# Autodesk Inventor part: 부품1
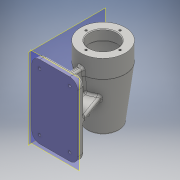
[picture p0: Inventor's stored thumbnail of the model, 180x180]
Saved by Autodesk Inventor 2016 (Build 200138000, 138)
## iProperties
Created: 2018-09
Part Number: 부품1
Material: Generic
Document SubType Name: Modeling
Designer: CAMTIC
Density: 1 g/cm^3
Appearance: Default
Author: CAMTIC
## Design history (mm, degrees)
sketch "스케치1"
  geometry: L1 (0, -79.513)-(0, 78.585) reference; L2 (-6.8, 0)-(40.8, 0) reference; L3 (0, 56)-(34, 56); L4 (34, 56)-(34, 28); L5 (34, 28)-(24.144, -52.27); L6 (0, -56)-(0, 56); A1 r 80 centre (0, 24) between (0, -56) and (24.144, -52.27); 2 further points
  constraints: 8 end point, 4 point on line, 2 point on circle, 1 centre point, 1 collinear, 1 horizontal, 1 vertical
  dimensions: "d0" = 34 distance of L3.start L3.end; "d1" = 28 distance of L3.end L4.end; "d3" = 56 distance between parallel lines of L3 L2; "d4" = 7 deg angle of L4 L5; "d39" = 80 radius of A1; "d40" = 112 distance from line of L3 L6.start
revolve "회전1" sketch "스케치1" stored, may be unused: angle "d5" = 90 deg
node "작업 평면1"
sketch "스케치2"
  geometry: L1 (35, 56)-(-35, 56); L2 (-35, 56)-(-35, -56); L3 (-35, -56)-(35, -56); L4 (35, -56)-(35, 56); L5 (49, 0)-(-49, 0) reference; L6 (0, -78.4)-(0, 78.4) reference; 1 further point
  constraints: 8 end point, 2 parallel, 1 horizontal, 1 perpendicular
  dimensions: "d7" = 112 distance between parallel lines of L3 L1; "d8" = 56 distance between parallel lines of L5 L1; "d9" = 70 distance between parallel lines of L2 L4; "d10" = 35 distance between parallel lines of L6 L4
extrude "돌출1" join sketch "스케치2" distance "d11" = 10; taper "d12" = 0 deg
sketch "스케치3"
  geometry: L1 (-35, -74)-(35, -74); L2 (-34.819, -63.503)-(-18.621, -19); L3 (-18.621, -19)-(18.621, -19); L4 (18.621, -19)-(34.819, -63.503); L5 (35, -74)-(-35, -74); L6 (35, -74)-(-35, -74) reference; L7 (-35, -64)-(35, -64) reference; L8 (35, -74)-(35, -64) reference; L9 (35, -64.529)-(35, -74); L10 (-35, -74)-(35, -74) reference; L11 (35, -74)-(-35, -74); L12 (-35, -74)-(-35, -64) reference; L13 (-35, -74)-(-35, -64.529); L14 (0, -95.6)-(0, 55.6) reference; L15 (-50.061, 0)-(50.061, 0) reference; A1 r 3 centre (32, -64.529) between (35, -64.529) and (34.819, -63.503); A2 r 3 centre (-32, -64.529) between (-34.819, -63.503) and (-35, -64.529); 3 further points
  constraints: 16 end point, 8 point on line, 4 point on circle, 4 tangent, 3 collinear, 2 centre point, 1 equal radius, 1 perpendicular
  dimensions: "d80" = 55 distance between parallel lines of L1 L3; "d81" = 20 deg angle of L4 L8; "d82" = 20 deg angle of L2 L12; "d83" = 36.04216 distance from line of L15.end L4; "d84" = 58.04206 distance from line of L15.end L2; "d85" = 3 radius of A1
extrude "돌출2" join sketch "스케치3" stored distance "d16" = 8; taper "d17" = 0 deg
sketch "스케치4"
  geometry: L1 (-14, 38)-(-64, 38); L2 (-64, -56)-(-64, 56) reference; L3 (-64, 38)-(-64, -38); L4 (-64, -56)-(-64, 56) reference; L5 (-64, -38)-(-14, -24.603); L6 (-14, -24.603)-(-14, 38); L7 (-34, 28)-(34, 28) reference; L8 (-74, 56)-(-64, 56) reference; L9 (-74, -56)-(-64, -56) reference; 3 further points
  constraints: 8 end point, 2 point on line, 1 horizontal, 1 perpendicular
  dimensions: "d18" = 105 deg angle of L4 L5; "d19" = 18 distance between parallel lines of L1 L8; "d20" = 18 distance from line of L3.end L9; "d21" = 50 distance between parallel lines of L3 L6
extrude "돌출3" join sketch "스케치4" stored distance "d22" = 8; taper "d23" = 0 deg
fillet "모깎기1" dims "d24" = 12
sketch "스케치5"
  geometry: L1 (-47.6, 0)-(47.6, 0) reference; L2 (0, -71.2)-(0, 77.2) reference; L3 (16, -47)-(16, -43); L4 (16, -43)-(17.5, -43); L5 (17.5, -43)-(17.5, -25); L6 (17.5, -25)-(21, -25); L7 (21, -25)-(21, -13); L8 (21, -13)-(24, -13); L9 (24, -13)-(24, 41); L10 (24, 41)-(21, 41); L11 (21, 41)-(21, 56); L12 (-34, 56)-(34, 56) reference; L13 (21, 56)-(0, 56); L14 (0, 56)-(0, -50); L15 (16, -47)-(10.5, -47); L16 (10.5, -47)-(10.5, -50); L17 (10.5, -50)-(0, -50); 1 further point
  constraints: 28 end point, 8 perpendicular, 4 point on line, 1 collinear, 1 horizontal, 1 midpoint
  dimensions: "d26" = 21 distance of L11.end L13.end; "d27" = 24 distance between parallel lines of L2 L9; "d29" = 17.5 distance between parallel lines of L2 L5; "d30" = 16 distance between parallel lines of L2 L3; "d31" = 10.5 distance between parallel lines of L2 L16; "d32" = 15 distance between parallel lines of L13 L10; "d33" = 54 distance between parallel lines of L10 L8; "d34" = 12 distance between parallel lines of L8 L6; "d35" = 18 distance between parallel lines of L6 L4; "d36" = 3 distance between parallel lines of L15 L17; "d37" = 4 distance between parallel lines of L4 L15
revolve "회전2" sketch "스케치5" stored, may be unused: angle "d38" = 90 deg
fillet "모깎기3" dims "d41" = 0.3
fillet "모깎기4" dims "d42" = 3
fillet "모깎기5" dims "d43" = 3
chamfer "모따기1" distance "d44" = 1; stored, may be unused: second distance "d45" = 2, angle "d46" = 45 deg
fillet "모깎기6" dims "d47" = 3
fillet "모깎기7" dims "d48" = 3
sketch "스케치6"
  geometry: A1 r 12 centre (-23, 44) between (-23, 56) and (-35, 44) reference; A2 r 12 centre (23, 44) between (35, 44) and (23, 56) reference; A3 r 12 centre (-23, -44) between (-35, -44) and (-23, -56) reference; A4 r 12 centre (23, -44) between (23, -56) and (35, -44) reference; 5 further points
  constraints: 4 coincident
hole "구멍1" sketch "스케치6" at (-23, 44), (23, 44), (-23, -44), (23, -44) diameter "d52" = 4; stored, may be unused: countersink angle "d56" = 90 deg, drill point angle "d58" = 0 deg; dims "d53" = 6, "d54" = 9.5, "d55" = 5.4, "d57" = 8
sketch "스케치7"
  geometry: L1 (0, 55.6)-(0, -95.6) reference; L2 (-49, 0)-(49, 0) reference; C1 r 7.5 at (0, 0) reference; A1 r 26 centre (0, 0) between (0, 26) and (-26, 0); 3 further points
  constraints: 4 point on circle, 4 point on line, 1 centre point, 1 coincident
  dimensions: "d59" = 52 diameter of A1
hole "구멍2" sketch "스케치7" diameter "d63" = 3.242; stored, may be unused: countersink angle "d67" = 90 deg, drill point angle "d69" = 118 deg; dims "d64" = 8, "d65" = 9.5, "d66" = 5.4, "d68" = 11
node "작업 평면2"
sketch "스케치8"
  geometry: L1 (74, 56)-(64, 56) reference; L2 (74, 56)-(74, 44) reference; 2 further points
  constraints: 1 other
  dimensions: "d71" = 56 distance from line of point (71, 0) L1; "d86" = 3 distance from line of L2 point (71, 0)
feature "엠보싱1" sketch "스케치8" dims "d73" = 0.5, "d74" = 0
fillet "모깎기19" dims "d87" = 3
fillet "모깎기20" dims "d88" = 3
fillet "모깎기21" dims "d89" = 3
fillet "모깎기22" dims "d90" = 3
node "솔리드1"
other parameters: "d6" = -74, "d70" = -35.5
